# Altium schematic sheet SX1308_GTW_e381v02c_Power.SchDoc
size B; DrawnBy: Erik Fountain; DocumentNumber: 4; SheetNumber: 4; SheetTotal: 5; PageSetup: Record=PageOptions|CenterHorizontal=True|CenterVertical=True|PrintScale=0.72|XCorrection=1.00|YCorrection=1.00|PrintKind=0|BorderSize=5000000|LeftOffset=0|BottomOffset=0|Orientation=2|PaperLength=1000|PaperWidth=1000|Scale=100|PaperSource=7|PrintQuality=-4|MediaType=1|DitherType=10|PaperKind=Letter|PrintScaleMode=1
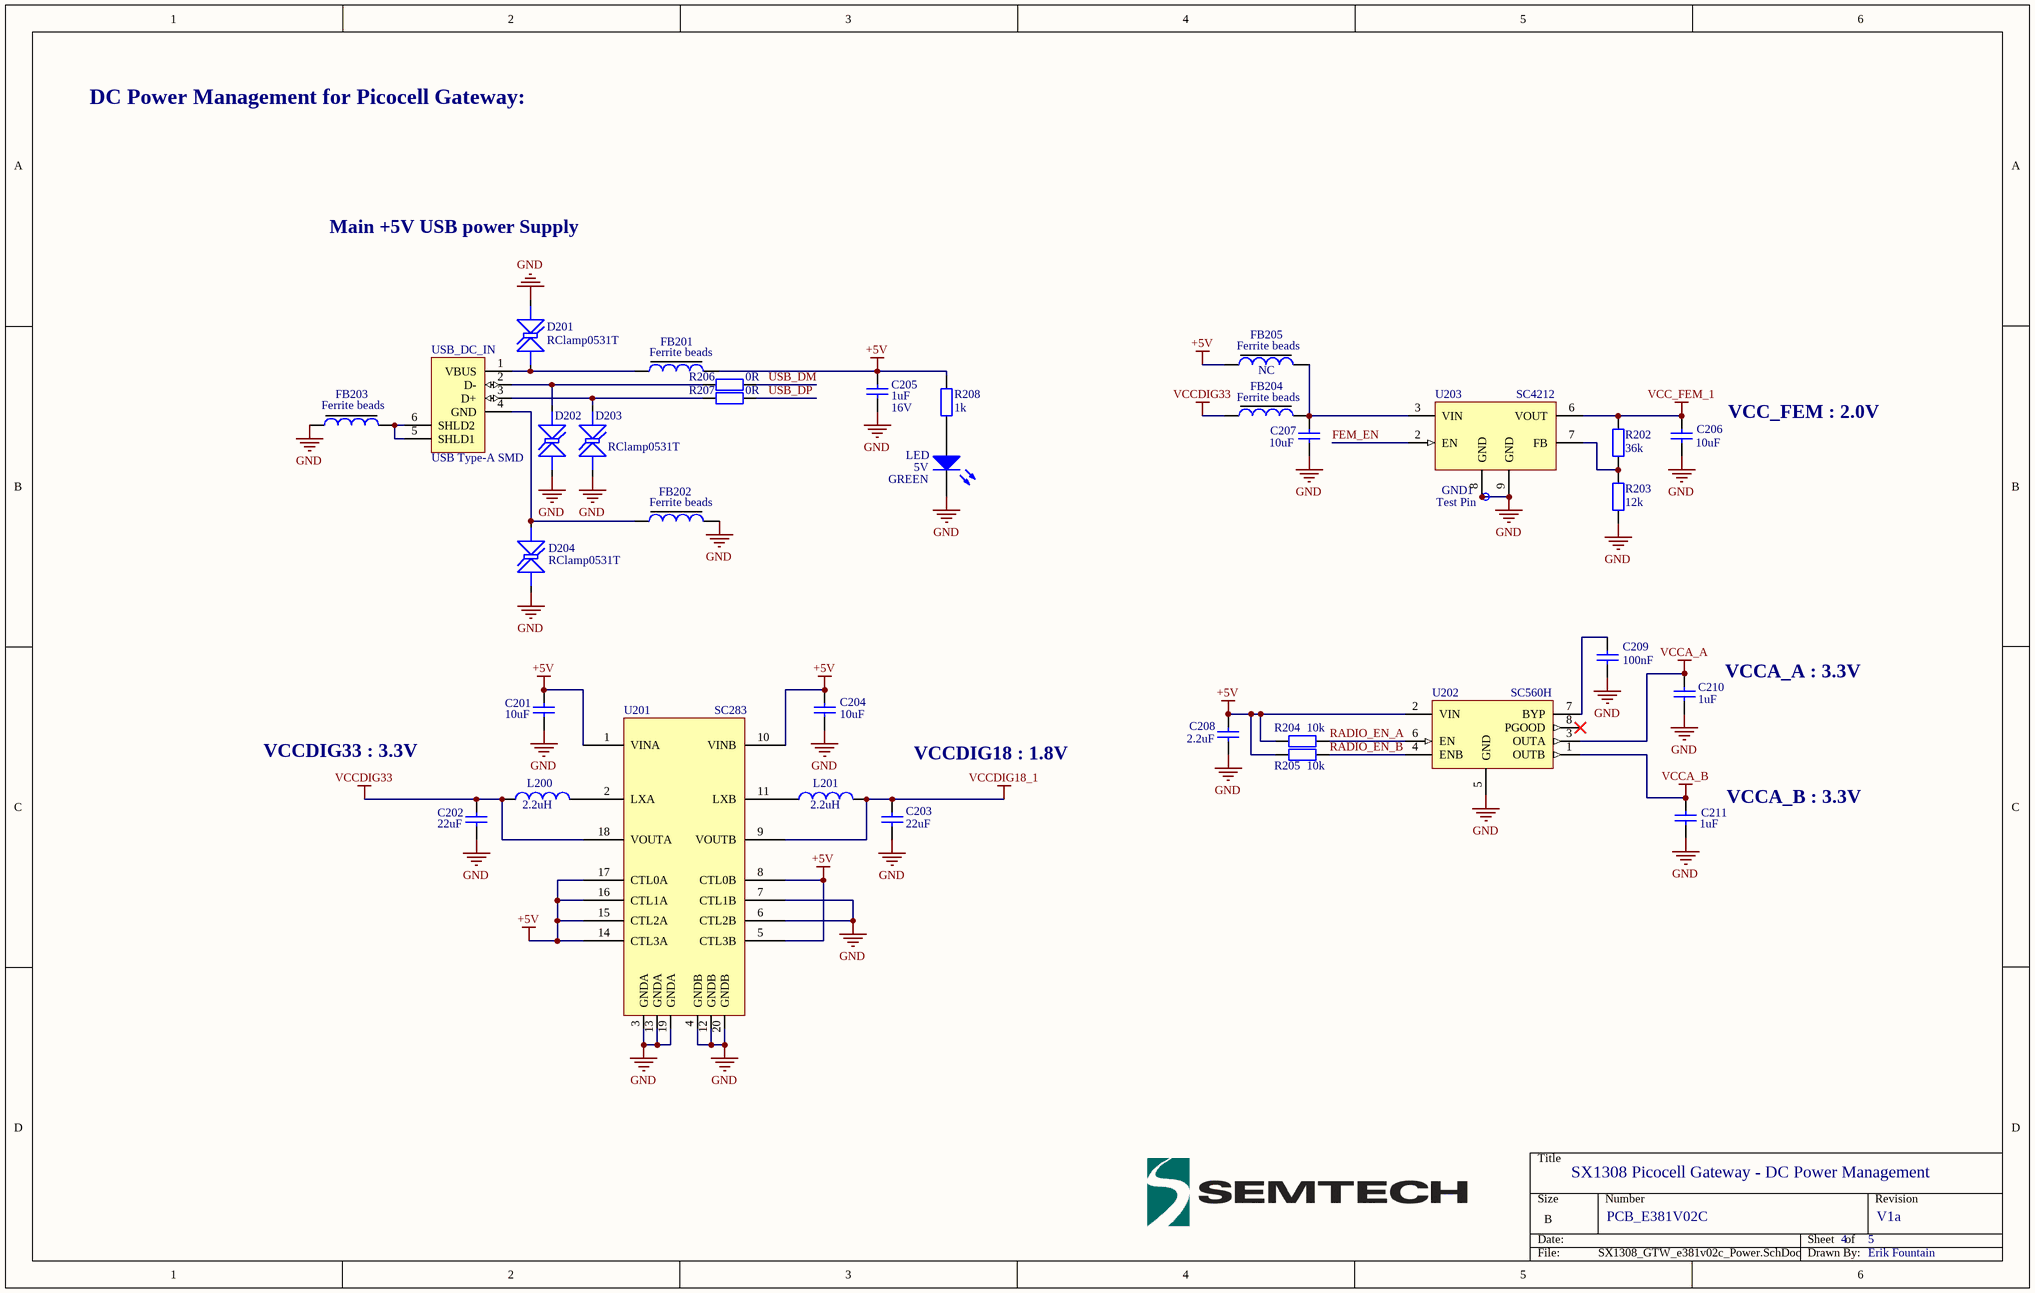
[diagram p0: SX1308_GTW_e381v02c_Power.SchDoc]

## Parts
5V  LED  Type: GREEN  [CD1608-0603]
C201  value 10uF  [C1206]  (hidden comment: Cap)
C202  value 22uF  [C1206]  (hidden comment: Cap)
C203  value 22uF  [C1206]  (hidden comment: Cap)
C204  value 10uF  [C1206]  (hidden comment: Cap)
C205  value 1uF  DC Voltage: 16V  [rlc_805_smd]  (hidden comment: Cap)
C206  value 10uF  [rlc_805_smd]  (hidden comment: Cap)
C207  value 10uF  [rlc_805_smd]  (hidden comment: Cap)
C208  value 2.2uF  [rlc_603_smd]  (hidden comment: Cap)
C209  value 100nF  [rlc_402_smd]  (hidden comment: Cap)
C210  value 1uF  [rlc_805_smd]  (hidden comment: Cap)
C211  value 1uF  [rlc_805_smd]  (hidden comment: Cap)
D201  RClamp0531T  [SLP1006P2T]
D202  RClamp0531T  [SLP1006P2T]  (value not drawn)
D203  RClamp0531T  [SLP1006P2T]
D204  RClamp0531T  [SLP1006P2T]
FB201  Ferrite beads  [rlc_402_smd]
FB202  Ferrite beads  [rlc_402_smd]
FB203  Ferrite beads  [rlc_402_smd]
FB204  Ferrite beads  [rlc_402_smd]
FB205  Ferrite beads  value NC  [rlc_402_smd]
GND1  Test Pin  [pin_1mm]
L200  value 2.2uH  [L4818]  (hidden comment: Inductor)
L201  value 2.2uH  [L4818]  (hidden comment: Inductor)
R202  value 36k  [rlc_402_smd]  (hidden comment: Resistor)
R203  value 12k  [rlc_402_smd]  (hidden comment: Resistor)
R204  value 10k  [rlc_402_smd]  (hidden comment: Resistor)
R205  value 10k  [rlc_402_smd]  (hidden comment: Resistor)
R206  value 0R  [rlc_402_smd]  (hidden comment: Resistor)
R207  value 0R  [rlc_402_smd]  (hidden comment: Resistor)
R208  value 1k  [rlc_402_smd]  (hidden comment: Resistor)
U201  SC283  [MLPQ-W18]
U202  SC560H  [MLPQ-UT8]
U203  SC4212  [MLPD-8 3x3mm]
USB_DC_IN  USB Type-A SMD  [Keystone USB Type 931]

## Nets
+5V: C201.1 C204.1 C205.1 C208.1 FB201.2 FB205.1 R204.1 R205.1 R208.1 U201.1(VINA) U201.5(CTL3B) U201.8(CTL0B) U201.10(VINB) U201.14(CTL3A) U201.15(CTL2A) U201.16(CTL1A) U201.17(CTL0A) U202.2(VIN)
GND: 5V.2(K) C201.2 C202.2 C203.2 C204.2 C205.2 C206.2 C207.2 C208.2 C209.1 C210.2 C211.2 D201.2(K) D202.2(K) D203.2(K) D204.2(K) FB202.2 FB203.1 GND1.1(pin) R203.2 U201.3(GNDA) U201.4(GNDB) U201.6(CTL2B) U201.7(CTL1B) U201.12(GNDB) U201.13(GNDA) U201.19(GNDA) U201.20(GNDB) U202.5(GND) U203.8(GND) U203.9(GND)
VCC_FEM_1: C206.1 R202.1 U203.6(VOUT)
VCCA_A: C210.1 U202.3(OUTA)
VCCA_B: C211.1 U202.1(OUTB)
VCCDIG18_1: C203.1 L201.2 U201.9(VOUTB)
VCCDIG33: C202.1 FB204.1 L200.1 U201.18(VOUTA)
FEM_EN: U203.2(EN)
RADIO_EN_A: R204.2 U202.6(EN)
RADIO_EN_B: R205.2 U202.4(ENB)
USB_DM: R206.2
USB_DP: R207.2
Net5V_1: 5V.1(A) R208.2
NetC207_1: C207.1 FB204.2 FB205.2 U203.3(VIN)
NetC209_2: C209.2 U202.7(BYP)
NetD201_1: D201.1(A) FB201.1 USB_DC_IN.1(VBUS)
NetD202_1: D202.1(A) R206.1 USB_DC_IN.2(D-)
NetD203_1: D203.1(A) R207.1 USB_DC_IN.3(D+)
NetD204_1: D204.1(A) FB202.1 USB_DC_IN.4(GND)
NetFB203_2: FB203.2 USB_DC_IN.5(SHLD1) USB_DC_IN.6(SHLD2)
NetL200_2: L200.2 U201.2(LXA)
NetL201_1: L201.1 U201.11(LXB)
NetR202_2: R202.2 R203.1 U203.7(FB)

Not connected (* = marked no-connect by the designer): U202 8(PGOOD)*

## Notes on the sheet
- DC Power Management for Picocell Gateway:
- Main +5V USB power Supply
- (near C206) VCC_FEM : 2.0V
- (near C210) VCCA_A : 3.3V
- VCCDIG33 : 3.3V
- VCCDIG18 : 1.8V
- (near C211) VCCA_B : 3.3V
- SX1308 Picocell Gateway - DC Power Management
- PCB_E381V02C
- V1a

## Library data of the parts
C201-C211 = Cap: Capacitor SMD
D201-D204 = RClamp0531T: Ultra Low Capacitance 1-line ESD Protection
FB201 FB202 FB204 = Ferrite beads: Value: VAL?
GND1 = test_pin
L200 L201 = Inductor: Code_IEC: 1005
R202-R208 = Resistor: Resistor SMD - IEC symbol version
U201 = SC283: SC283 - Dual Channel 2.5MHz, 1.8A  Synchronous Step-Down Regulator
U202 = SC560H: SC560H - Dual Output Low Noise LDO  Linear Regulator
U203 = SC4212: SC4212 - Very Low Input /Very Low Dropout  1Amp Regulator With Enable
USB_DC_IN = USB Type-A SMD: USB 2.0 SMT, Type A, Receptacle, 4 Position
